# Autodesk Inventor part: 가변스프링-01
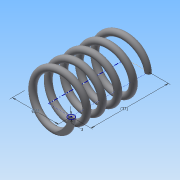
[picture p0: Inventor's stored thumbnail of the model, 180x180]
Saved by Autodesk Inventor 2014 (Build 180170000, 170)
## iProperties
Created: 2015-09
Part Number: 가변스프링-01
Material: 강철, 탄소
Document SubType Name: Modeling
Designer: study
Density: 1 g/cm^3
Appearance: 반연마
Author: study
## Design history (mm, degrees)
sketch "스케치1"
  geometry: L1 (0, 0)-(11, 0); L2 (11, 0)-(11, 40.095); L3 (11, 40.095)-(0, 40.095); L4 (0, 40.095)-(0, 0); C1 r 1.5 at (11, 0)
  constraints: 8 end point, 2 parallel, 1 centre point, 1 coincident, 1 horizontal, 1 perpendicular
  dimensions: "d0" = 40.0955 distance of L1.end L2.end (derived); "d1" = 22 diameter of L2 L4; "d2" = 3 diameter of C1
feature "코일1" sketch "스케치1" pitch "d3" = 10; turns "d5" = 5; dims "d4" = 40.0955 (= d0), "d6" = 0, angle "d7" = 90 deg, angle "d8" = 90 deg, "d9" = 0, "d10" = 0
node "작업 평면1"
sketch "스케치2"
  geometry: L1 (-12.5, 0)-(-9.5, 0) reference; 1 further point
  constraints: 1 horizontal alignment
extrude "돌출1" cut sketch "스케치2" stored distance "d12" = 10; taper "d13" = 0 deg
node "작업 평면2"
sketch "스케치3"
  geometry: L1 (-9.5, 0)-(-12.5, 0) reference; 1 further point
  constraints: 1 horizontal alignment
extrude "돌출2" cut sketch "스케치3" distance "d15" = 10; taper "d16" = 0 deg
node "솔리드1"
node "절단 모서리 투영1"
node "절단 모서리 투영2"
other parameters: "d11" = 0, "d14" = 40.0955 (= d0)
